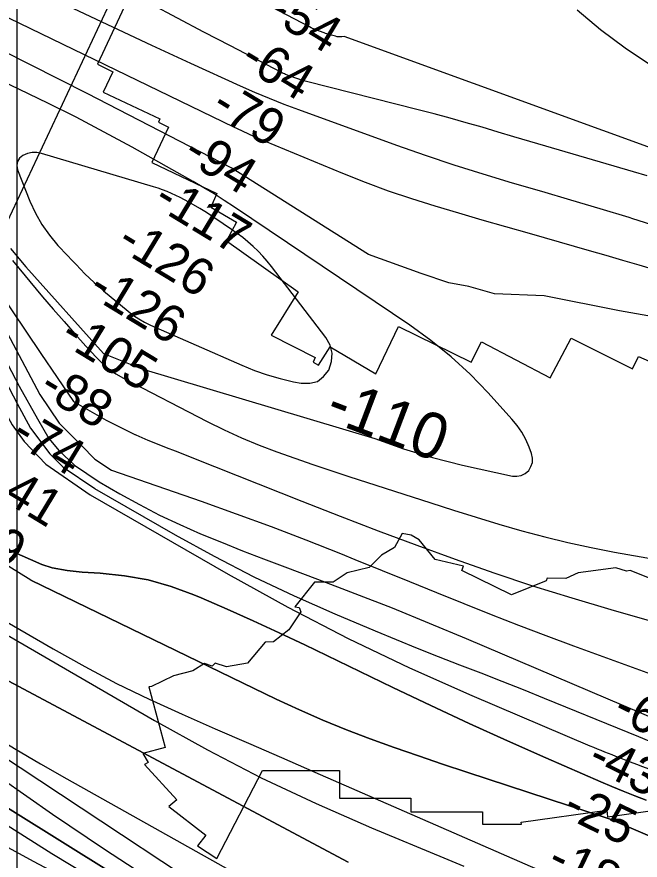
# Model space of a CAD drawing. Extents: x 3263578 to 3301413, y 764927 to 798602.
# Drawn here: x 3280833 to 3281967, y 783206 to 784740 of the extents above; entities that cross this region are included whole.
import ezdxf

# ---------------------------------------------------------------- set-up
doc = ezdxf.new("R2010")
doc.units = 0
for name, color, linetype in [('V-GRID-MAJR', 7, 'Continuous'), ('V-RIVR-RANG', 7, 'Continuous'), ('V-RRAP-RVMT', 7, 'Continuous'), ('V-TOPO-DPTH', 7, 'Continuous'), ('V-TOPO-MAJR', 7, 'Continuous'), ('V-TOPO-MINR', 7, 'Continuous'), ('V-TOPO-MINR-IDEN', 7, 'Continuous'), ('V-TOPO-WATR', 7, 'Continuous')]:
    doc.layers.add(name, color=color, linetype=linetype)

msp = doc.modelspace()

# ---------------------------------------------------------------- linework, layer by layer
at = {"layer": 'V-GRID-MAJR'}
msp.add_spline([(3280833.3, 775830.4), (3280833.3, 781889.1), (3280833.3, 787951.1), (3280833.3, 794013.2), (3280833.3, 794016.5)], degree=3, dxfattribs=at)
at = {"layer": 'V-RIVR-RANG'}
msp.add_line((3280392.6, 783467.5), (3281107, 784989.2), dxfattribs=at)
at = {"layer": 'V-RRAP-RVMT'}
for points in [[(3281046.4, 784797.3), (3280979.3, 784654), (3281007.5, 784640.2), (3280989.8, 784603), (3281092.9, 784554.5), (3281090.5, 784548.9), (3281109, 784539.5), (3281078.4, 784475.5), (3281196.8, 784419.1), (3281185.6, 784394.3), (3281232.2, 784366.9), (3281214.3, 784332.6), (3281344.9, 784239.9), (3281295.8, 784161.2), (3281375.9, 784120.7), (3281371.8, 784111.8), (3281381.8, 784106.6), (3281403, 784140.1), (3281485.8, 784090.8)], [(3281485.8, 784090.8), (3281527, 784176.8)], [(3281527, 784176.8), (3281659.2, 784111.8), (3281678.1, 784148.8), (3281803, 784083.6), (3281841.2, 784155.5), (3281953.1, 784099.7), (3281963.9, 784122.4), (3282083.6, 784070.4), (3282087.1, 784078.4), (3282110.2, 784068.8), (3282133.9, 784114.1), (3282266.9, 784050.1), (3282256.8, 784028.8), (3282374.6, 783971.7), (3282287.6, 783777.8), (3282370.5, 783940), (3282499.2, 783875.4), (3282489.6, 783855.9)], [(3281645.5, 783741.2), (3281593.7, 783753), (3281564.9, 783789), (3281550.3, 783797.4), (3281534, 783800.6), (3281519.7, 783774.8), (3281496.4, 783761), (3281474, 783738.6), (3281433.8, 783728.6), (3281408.6, 783711.6), (3281374.6, 783712.1), (3281338.9, 783667.2)], [(3282111.5, 783656.7), (3282110.1, 783657), (3282097.5, 783653), (3282089.8, 783656.1), (3282083, 783653.5), (3282082.9, 783658.5), (3282075.9, 783663.5), (3282077.8, 783672.5), (3282067.8, 783675), (3282048.2, 783686.4), (3282022.9, 783684.8), (3281991.4, 783708.3), (3281983.8, 783719.1), (3281948.5, 783733.3), (3281941.9, 783731.9), (3281922.7, 783737.9), (3281854.3, 783729), (3281831.8, 783718.8), (3281797.8, 783719.2), (3281796, 783714.6), (3281732.7, 783688.9), (3281642.2, 783733), (3281645.5, 783741.2)], [(3281338.9, 783667.2), (3281346.4, 783665.8), (3281349.5, 783657.8), (3281327.4, 783625.4), (3281299.7, 783603.1), (3281284.5, 783602.8), (3281252.6, 783564.3), (3281214.2, 783558.1), (3281193.8, 783564.7), (3281188, 783558.9), (3281174, 783564), (3281153, 783550.6), (3281117.9, 783541.3), (3281077.9, 783521.9), (3281073.2, 783521.3)], [(3281073.2, 783521.3), (3281102.5, 783411), (3281061.8, 783399.9), (3281072, 783383.8), (3281065, 783379.9), (3281123.8, 783315.9), (3281109.4, 783304), (3281176.9, 783251.7), (3281161.8, 783232), (3281196.8, 783209.1), (3281280, 783369.5)], [(3281280, 783369.5), (3281419.9, 783369.3), (3281419.9, 783318.8), (3281549.9, 783318.7), (3281549.9, 783294.2), (3281679.9, 783294.1), (3281680, 783271.6), (3281751.1, 783271.5), (3281750.4, 783275.4), (3281906.1, 783296.9), (3281907.7, 783285.1), (3282054.3, 783305.5), (3282054.5, 783299.1), (3282060, 783299.2)]]:
    msp.add_lwpolyline(points, dxfattribs=at)
at = {"layer": 'V-TOPO-DPTH'}
for points in [[(3280190.6, 784677.4), (3280301.9, 784587.8), (3280409.7, 784468.3), (3280489.5, 784360), (3280600.9, 784173.4), (3280669.5, 784076.4), (3280702.9, 784014.8), (3280723.3, 783957), (3280738.1, 783910.4), (3280749.2, 783871.3), (3280769.6, 783835.8), (3280782.5, 783813.4), (3280801.1, 783791), (3280821.6, 783768.6), (3280878, 783744)], [(3280878, 783744), (3280821.6, 783768.6), (3280801.1, 783791), (3280782.5, 783813.4), (3280769.6, 783835.8), (3280749.2, 783871.3), (3280738.1, 783910.4), (3280723.3, 783957), (3280702.9, 784014.8), (3280669.5, 784076.4), (3280600.9, 784173.4), (3280489.5, 784360), (3280409.7, 784468.3), (3280301.9, 784587.8), (3280190.6, 784677.4)], [(3280858.2, 783715.4), (3280760.1, 783776.2), (3280709.9, 783828.5), (3280678.4, 783890.1), (3280650.7, 783972.1), (3280615.6, 784089.6), (3280563.6, 784175.4), (3280496.8, 784294.8), (3280443, 784369.4), (3280366.8, 784459.1), (3280296.2, 784541.2), (3280236.8, 784619.6), (3280177.7, 784667.3)], [(3280858.2, 783715.4), (3280760.1, 783776.2), (3280709.9, 783828.5), (3280678.4, 783890.1), (3280650.7, 783972.1), (3280615.6, 784089.6), (3280563.6, 784175.4), (3280496.8, 784294.8), (3280443, 784369.4), (3280366.8, 784459.1), (3280296.2, 784541.2), (3280236.8, 784619.6), (3280177.7, 784667.3)], [(3280878, 783744), (3280897.3, 783738.1), (3280924.4, 783733.1), (3280951.9, 783730), (3280984.6, 783728.2), (3281028.4, 783723.6), (3281071.5, 783715.9), (3281113.5, 783703.8), (3281154.9, 783688.8), (3281168.3, 783683.1), (3281215.7, 783662.6), (3281262.9, 783641.6), (3281309.8, 783619.9), (3281356.5, 783597.8), (3281517.1, 783520.2), (3281586.3, 783487.3), (3281655.7, 783454.9), (3281725.5, 783423.4), (3281795.6, 783392.3), (3281895.2, 783348.9), (3281915.7, 783340.2), (3281936.3, 783331.6), (3281957, 783323.4), (3281977.8, 783315.5)], [(3281977.8, 783315.5), (3281957, 783323.4), (3281936.3, 783331.6), (3281915.7, 783340.2), (3281895.2, 783348.9), (3281795.6, 783392.3), (3281725.5, 783423.4), (3281655.7, 783454.9), (3281586.3, 783487.3), (3281517.1, 783520.2), (3281356.5, 783597.8), (3281309.8, 783619.9), (3281262.9, 783641.6), (3281215.7, 783662.6), (3281168.3, 783683.1), (3281154.9, 783688.8), (3281113.5, 783703.8), (3281071.5, 783715.9), (3281028.4, 783723.6), (3280984.6, 783728.2), (3280951.9, 783730), (3280924.4, 783733.1), (3280897.3, 783738.1), (3280878, 783744)], [(3283979.6, 782089.4), (3282888, 782862.5), (3281912.3, 783281), (3281651.6, 783366.2), (3281607.5, 783380.8), (3281563.5, 783395.7), (3281519.6, 783411.1), (3281475.8, 783426.8), (3281432.4, 783443.3), (3281389.4, 783460.7), (3281346.9, 783479.4), (3281304.8, 783499), (3280858.2, 783715.4)], [(3283979.6, 782089.4), (3282888, 782862.5), (3281912.3, 783281), (3281651.6, 783366.2), (3281607.5, 783380.8), (3281563.5, 783395.7), (3281519.6, 783411.1), (3281475.8, 783426.8), (3281432.4, 783443.3), (3281389.4, 783460.7), (3281346.9, 783479.4), (3281304.8, 783499), (3280858.2, 783715.4)], [(3280807.9, 783643.1), (3280898.7, 783590.4), (3280956.2, 783558.3), (3281014.4, 783527.6), (3281073.5, 783498.9), (3281133.4, 783471.6), (3281193.8, 783445.2), (3281254.1, 783418.9), (3281314.5, 783392.6), (3281374.9, 783366.2), (3281790.2, 783185.2)], [(3280807.9, 783643.1), (3280898.7, 783590.4), (3280956.2, 783558.3), (3281014.4, 783527.6), (3281073.5, 783498.9), (3281133.4, 783471.6), (3281193.8, 783445.2), (3281254.1, 783418.9), (3281314.5, 783392.6), (3281374.9, 783366.2), (3281790.2, 783185.2)], [(3281435.6, 783202.7), (3281389.2, 783227.1), (3280753.8, 783565.5)], [(3281435.6, 783202.7), (3281389.2, 783227.1), (3280753.8, 783565.5)], [(3280689.6, 783473.1), (3281429.6, 782984.4)], [(3280689.6, 783473.1), (3281429.6, 782984.4)], [(3283888.6, 781898.9), (3282782, 782505.4), (3282768.2, 782511.2), (3282754.3, 782516.7), (3282740.3, 782521.9), (3282726.2, 782526.9), (3281705.6, 782792.3), (3281690.7, 782798.6), (3281676, 782805.1), (3281661.5, 782812.2), (3281647.2, 782819.6), (3281449.7, 782925.5), (3281337.4, 782987.1), (3281225.9, 783050.2), (3281115.7, 783115.5), (3281006.4, 783182.2), (3280644.3, 783408)]]:
    msp.add_lwpolyline(points, dxfattribs=at)
at = {"layer": 'V-TOPO-MAJR'}
for points in [[(3281472.5, 784307.7), (3281223, 784465.5), (3280961.7, 784600), (3280857.4, 784653.2), (3280752.9, 784705.9), (3280647.9, 784757.8)], [(3281985.6, 784652.4), (3281939.5, 784683.5), (3281894.9, 784716.5), (3281852.6, 784752.4)], [(3280197.5, 784691.9), (3280326.2, 784597), (3280432.2, 784509.2), (3280486.1, 784458.8), (3280534.4, 784410.2), (3280593.8, 784335.5), (3280666.3, 784249.7), (3280735, 784160.1), (3280766.5, 784104.1), (3280788.7, 784063.1), (3280824, 783997.8), (3280846.3, 783967.9), (3280885.3, 783926.8), (3280966.1, 783870.6)], [(3282227.2, 783780.1), (3282315.8, 783864), (3282359.5, 783954.1), (3282359.6, 784010.9), (3282353, 784054.3), (3282333.1, 784084.4), (3282279.7, 784121.3), (3282186.2, 784158.3), (3282042.7, 784185.4), (3281929.1, 784205.7), (3281792.2, 784232.8), (3281702, 784236.3), (3281655.3, 784249.8), (3281618.6, 784256.6), (3281568.5, 784273.4), (3281472.5, 784307.7)], [(3280824.6, 784297), (3280879.7, 784231.1), (3280899, 784208.4), (3280918.6, 784185.8), (3280938.4, 784163.5), (3280958.5, 784141.3), (3280977.8, 784120.3), (3280988.9, 784109.5), (3281000.6, 784099.5), (3281013.2, 784090.8), (3281026.6, 784083), (3281179.2, 784004), (3281210.2, 783988.7), (3281241.6, 783974.3), (3281273.5, 783961.1), (3281305.8, 783948.8), (3281338.5, 783937.3), (3281371.2, 783926), (3281404, 783915), (3281436.9, 783904.1), (3281585.8, 783855.9), (3281627.1, 783842.8), (3281668.5, 783830), (3281710, 783817.6), (3281751.6, 783805.4), (3281793.4, 783794.2), (3281835.4, 783783.8), (3281877.7, 783774.7), (3281920.2, 783766.6), (3282135, 783728.7)], [(3280966.1, 783870.6), (3281217.4, 783726.3), (3281325.9, 783666.6), (3281435.7, 783609.5), (3281547.4, 783556.3), (3281660.4, 783505.8), (3281875.2, 783414.2), (3281881.8, 783411.5), (3281888.5, 783408.7), (3281895.2, 783406), (3281901.8, 783403.4), (3281908.6, 783400.8), (3281915.3, 783398.2), (3281921.9, 783395.6), (3281928.6, 783392.9), (3281937.6, 783389.4), (3281948.8, 783385), (3281960.1, 783380.7), (3281971.3, 783376.5), (3281982.6, 783372.3), (3282299.1, 783257.3), (3282408.4, 783218.8), (3282518.1, 783181.7)]]:
    msp.add_lwpolyline(points, dxfattribs=at)
at = {"layer": 'V-TOPO-MINR'}
for points in [[(3282369.7, 784362.5), (3281428.1, 784704.7), (3281424.1, 784703.8), (3281420.1, 784703.7), (3281415.9, 784704.2), (3281412.9, 784704.9), (3281410.2, 784705.5), (3281407.5, 784706.2), (3281404.9, 784706.9), (3281402.3, 784707.7), (3281399.6, 784708.5), (3281397, 784709.3), (3281394.5, 784710.2), (3281391.9, 784711.1), (3281377.1, 784716.7), (3281374.1, 784717.9), (3281371, 784719.2), (3281368.1, 784720.6), (3281365.1, 784722.1), (3281121.6, 784850.3)], [(3280279, 784758.1), (3280497.5, 784568.6), (3280620.2, 784456.6), (3280768.8, 784286.7), (3280876.5, 784128), (3280935.9, 784040.3), (3280995.4, 784006.7), (3281047.7, 783980.5)], [(3282009.3, 784355.3), (3281953.4, 784373.1), (3281947, 784375.1), (3281894, 784391), (3281840.9, 784406.9), (3281787.8, 784422.5), (3281734.6, 784438), (3281681.5, 784453.9), (3281628.7, 784470.5), (3281576.2, 784488.1), (3281524, 784506.5), (3281346.1, 784570.9), (3281319.2, 784581), (3281292.5, 784591.5), (3281266, 784602.7), (3281239.7, 784614.3), (3281149.5, 784655.4), (3281078.4, 784688.1), (3281007.4, 784721.3), (3280936.7, 784754.9)], [(3281980, 784451.2), (3281954.6, 784458.1), (3281795.2, 784505.1), (3281766.2, 784513.7), (3281737.3, 784522.3), (3281708.3, 784530.8), (3281679.4, 784539.4), (3281650.4, 784547.8), (3281621.3, 784556), (3281592.1, 784563.8), (3281562.9, 784571.4), (3281359.9, 784622.8), (3281352.8, 784624.7), (3281345.7, 784626.8), (3281338.7, 784629.2), (3281331.8, 784631.7), (3281321.8, 784635.6), (3281319.9, 784636.4), (3281318.1, 784637.2), (3281316.2, 784638.1), (3281314.4, 784639), (3281221.5, 784687.3), (3281173.3, 784712.5), (3281125.1, 784737.8), (3281077, 784763.3)], [(3280256.9, 784738), (3280372.9, 784645.3), (3280529, 784512.7), (3280614.5, 784424.9), (3280737.1, 784283), (3280804, 784186), (3280874.4, 784053.5), (3280909.7, 784001.3), (3280950.6, 783960.2), (3280974.7, 783935.9), (3281005.3, 783915.8)], [(3281995.6, 784279.2), (3281965.4, 784288.3), (3281935.2, 784297.2), (3281905, 784306), (3281874.7, 784314.7), (3281765.5, 784346), (3281722.5, 784358.3), (3281679.6, 784370.7), (3281636.8, 784383.3), (3281593.9, 784395.8), (3281551.3, 784409.2), (3281509, 784423.4), (3281467.2, 784438.9), (3281425.7, 784455.4), (3281285.2, 784513.7), (3281270.7, 784519.8), (3281256.3, 784526.1), (3281242.1, 784532.7), (3281227.9, 784539.4), (3280798.7, 784746.8)], [(3280226.1, 784709.7), (3280361.6, 784613.7), (3280504.8, 784503.4), (3280614.4, 784385.8), (3280701.7, 784285), (3280753.7, 784215.9), (3280794.5, 784148.7), (3280837.2, 784068.5), (3280870.6, 784008.8), (3280891, 783973.4), (3280909.6, 783951), (3280937.4, 783924.8), (3280982.5, 783894.2)], [(3280214.3, 784699), (3280367.1, 784591.3), (3280488, 784492.3), (3280554.9, 784413.9), (3280651.5, 784303.7), (3280735.1, 784201), (3280781.5, 784132), (3280811.1, 784079.8), (3280833.4, 784036.9), (3280857.5, 783992.1), (3280892.8, 783945.4), (3280916.9, 783921.1), (3280974.9, 783882)], [(3280190.6, 784677.4), (3280301.9, 784587.8), (3280409.7, 784468.3), (3280489.5, 784360), (3280600.9, 784173.4), (3280669.5, 784076.4), (3280702.9, 784014.8), (3280723.3, 783957), (3280738.1, 783910.4), (3280749.2, 783871.3), (3280769.6, 783835.8), (3280782.5, 783813.4), (3280801.1, 783791), (3280821.6, 783768.6), (3280878, 783744)], [(3280858.2, 783715.4), (3280760.1, 783776.2), (3280709.9, 783828.5), (3280678.4, 783890.1), (3280650.7, 783972.1), (3280615.6, 784089.6), (3280563.6, 784175.4), (3280496.8, 784294.8), (3280443, 784369.4), (3280366.8, 784459.1), (3280296.2, 784541.2), (3280236.8, 784619.6), (3280177.7, 784667.3)], [(3280821.1, 784318.9), (3280849.3, 784285.3), (3280990.4, 784128.1), (3281060.3, 784099.8), (3281483.9, 783973), (3281536.2, 783954.2), (3281589.4, 783938.6), (3281643.4, 783925), (3281734.4, 783904.9), (3281742.8, 783904.6), (3281750.6, 783905.8), (3281757.6, 783909.6), (3281764.1, 783915), (3281768.3, 783922.2), (3281770.9, 783929.8), (3281771, 783937.7), (3281769.4, 783946), (3281765, 783957.5), (3281758.9, 783971.3), (3281751.8, 783984.5), (3281743.2, 783996.8), (3281733.7, 784008.6), (3281690.5, 784056.2), (3281657.4, 784090), (3281622.9, 784122.1), (3281586.2, 784151.6), (3281548, 784179.4), (3281228.8, 784394.3), (3281210.3, 784406.4), (3281191.7, 784418.2), (3281172.8, 784429.5), (3281153.8, 784440.5), (3281042.5, 784503), (3280991.9, 784530.7), (3280940.9, 784557.6), (3280889.3, 784583.4), (3280837.4, 784608.4), (3280786.8, 784632.1)], [(3281243.8, 784338.8), (3281233.8, 784346.3), (3281223.6, 784353.5), (3281178, 784384.2), (3281175, 784386.2), (3281171.9, 784388.1), (3281168.7, 784390), (3281165.5, 784391.9), (3281145.5, 784403.1), (3281137.8, 784407.3), (3281130, 784411.4), (3281122.2, 784415.2), (3281114.3, 784418.9), (3281106.2, 784422.4), (3281098.1, 784425.6), (3281089.8, 784428.5), (3281081.5, 784431.2), (3280877.8, 784491.8), (3280869, 784493.3), (3280860.4, 784493.4), (3280851.9, 784491.5), (3280843.6, 784488.3), (3280837.7, 784483), (3280833.8, 784477), (3280832.9, 784469.9), (3280834, 784462.1), (3280856.5, 784404.9), (3280866.5, 784383.1), (3280878.1, 784362.3), (3280892, 784343), (3280907.4, 784324.6), (3280924.8, 784306.1), (3280932.7, 784297.8), (3280940.7, 784289.5), (3280948.7, 784281.2), (3280956.8, 784273.1), (3280965, 784265.1), (3280973.3, 784257.2), (3280981.9, 784249.6), (3280990.6, 784242.1), (3281035.6, 784204.6), (3281045.1, 784197.3), (3281054.9, 784190.7), (3281065.2, 784184.9), (3281075.9, 784179.6), (3281242.2, 784106.4), (3281265.2, 784097.2), (3281288.4, 784089), (3281312.1, 784082.2), (3281336.2, 784076.5), (3281350.3, 784073.6), (3281365.7, 784073.7), (3281379.6, 784077.2), (3281390.9, 784085.8), (3281400.7, 784097.8), (3281405.3, 784113.2), (3281406.5, 784128.2), (3281402.6, 784142.8), (3281395.3, 784157), (3281296.2, 784285.9), (3281288.4, 784295.6), (3281280.3, 784305), (3281271.6, 784313.9), (3281262.7, 784322.6), (3281253.3, 784330.8), (3281243.8, 784338.8)], [(3281043.8, 783982.3), (3281055, 783977.2), (3281071.4, 783970.2), (3281087.9, 783963.6), (3281104.5, 783957.1), (3281121.1, 783950.6), (3281137.7, 783944.1), (3281154.2, 783937.5), (3281351.5, 783859.3), (3281420.9, 783832.1), (3281490.5, 783805.4), (3281560.3, 783779.3), (3281630.3, 783753.7), (3281700.6, 783729.1), (3281771.3, 783705.4), (3281842.4, 783683.2), (3281913.8, 783662), (3282053.1, 783622.1)], [(3281005.3, 783915.8), (3281168.1, 783859), (3281231.8, 783836.3), (3281295.3, 783812.9), (3281358.5, 783788.7), (3281421.5, 783763.9), (3281447.9, 783753.3), (3281497.4, 783733.3), (3281547, 783713.2), (3281596.5, 783693.2), (3281646, 783673.1), (3281695.6, 783653.2), (3281745.4, 783633.7), (3281795.3, 783614.8), (3281845.5, 783596.3), (3282012.2, 783535.7)], [(3280982.5, 783894.2), (3281019.9, 783872.7), (3281055.9, 783852.9), (3281092.4, 783834), (3281129.6, 783816.6), (3281167.2, 783800), (3281205.2, 783784.4), (3281243.4, 783769), (3281281.8, 783754.1), (3281320.2, 783739.5), (3281379.6, 783717.4), (3281447.7, 783691.4), (3281515.6, 783664.9), (3281583, 783637.4), (3281650.3, 783609.4), (3282002.2, 783459.7)], [(3280974.3, 783882.4), (3281121, 783798.1), (3281192.1, 783759.1), (3281264, 783721.8), (3281337.3, 783687.1), (3281411.4, 783654.2), (3281484.7, 783623.3), (3281522.9, 783607.5), (3281561.2, 783591.8), (3281599.7, 783576.7), (3281638.3, 783561.7), (3281677, 783546.9), (3281715.5, 783531.8), (3281754, 783516.5), (3281792.3, 783501), (3281944.5, 783438.8), (3281963.7, 783431.1), (3281982.9, 783423.5)], [(3280878, 783744), (3280897.3, 783738.1), (3280924.4, 783733.1), (3280951.9, 783730), (3280984.6, 783728.2), (3281028.4, 783723.6), (3281071.5, 783715.9), (3281113.5, 783703.8), (3281154.9, 783688.8), (3281168.3, 783683.1), (3281215.7, 783662.6), (3281262.9, 783641.6), (3281309.8, 783619.9), (3281356.5, 783597.8), (3281517.1, 783520.2), (3281586.3, 783487.3), (3281655.7, 783454.9), (3281725.5, 783423.4), (3281795.6, 783392.3), (3281895.2, 783348.9), (3281915.7, 783340.2), (3281936.3, 783331.6), (3281957, 783323.4), (3281977.8, 783315.5)], [(3280858.2, 783715.4), (3281304.8, 783499), (3281346.9, 783479.4), (3281389.4, 783460.7), (3281432.4, 783443.3), (3281475.8, 783426.8), (3281519.6, 783411.1), (3281563.5, 783395.7), (3281607.5, 783380.8), (3281651.6, 783366.2), (3281912.3, 783281), (3282888, 782862.5), (3283979.6, 782089.4)], [(3280807.9, 783643.1), (3280898.7, 783590.4), (3280956.2, 783558.3), (3281014.4, 783527.6), (3281073.5, 783498.9), (3281133.4, 783471.6), (3281193.8, 783445.2), (3281254.1, 783418.9), (3281314.5, 783392.6), (3281374.9, 783366.2), (3281790.2, 783185.2)], [(3280796.4, 783626.6), (3281083.4, 783460.1), (3281179.8, 783406.6), (3281277.6, 783355.8), (3281377.3, 783309), (3281478.3, 783264.7), (3281609.5, 783210.5), (3281645.9, 783195.3)], [(3280753.8, 783565.5), (3281389.2, 783227.1), (3281435.6, 783202.7)], [(3280700.9, 783489.4), (3280735.5, 783467.1), (3280782, 783437.9), (3280828.8, 783409.1), (3280876.1, 783381.3), (3280923.8, 783354), (3281707.7, 782914.5), (3281716.8, 782910), (3281726.1, 782906.2), (3281735.7, 782903.4), (3282698.9, 782583.9), (3282734.1, 782571.4), (3282769.1, 782558.2), (3282803.8, 782544.3), (3282838.2, 782529.8), (3283666.8, 782075.8)], [(3280672.4, 783448.4), (3280804, 783355.1), (3280897.8, 783289.9), (3280992.3, 783225.9), (3281088.1, 783163.7), (3281184.6, 783102.6), (3281293.8, 783035), (3281357.2, 782996.5), (3281421.1, 782958.8), (3281485.7, 782922.3), (3281550.7, 782886.6), (3281664.9, 782825.3), (3281673.2, 782821), (3281681.7, 782816.9), (3281690.3, 782813.1), (3281698.9, 782809.4), (3282738.2, 782538.4), (3282759.2, 782530.6), (3282780.1, 782522.2), (3282800.7, 782513.6), (3283832.9, 781945.9)], [(3280644.3, 783408), (3281006.4, 783182.2), (3281115.7, 783115.5), (3281225.9, 783050.2), (3281337.4, 782987.1), (3281449.7, 782925.5), (3281647.2, 782819.6), (3281661.5, 782812.2), (3281676, 782805.1), (3281690.7, 782798.6), (3281705.6, 782792.3), (3282726.2, 782526.9), (3282740.3, 782521.9), (3282754.3, 782516.7), (3282768.2, 782511.2), (3282782, 782505.4), (3283888.6, 781898.9)], [(3280630.5, 783388.1), (3280789.5, 783285.4), (3280896.7, 783218.1), (3281004.9, 783152.6)], [(3280610, 783358.7), (3280657.9, 783326.6), (3280708, 783294.2), (3280758.7, 783262.9), (3280810.4, 783233.1), (3280862.7, 783204.3), (3281611.7, 782807.8), (3281638, 782794.4), (3281664.6, 782781.5), (3281691.6, 782769.6), (3282392.9, 782572.2), (3282414.3, 782567.9), (3282744.5, 782489.1), (3283892.6, 781840)]]:
    msp.add_lwpolyline(points, dxfattribs=at)
at = {"layer": 'V-TOPO-WATR'}
msp.add_lwpolyline([(3280689.6, 783473.1), (3281429.6, 782984.4)], dxfattribs=at)

# ---------------------------------------------------------------- texts
at = {"layer": 'V-RIVR-RANG'}
for s, rotation, p in [('-54', 328.7494, (3281285.9, 784739.1)), ('-64', 328.7494, (3281235.6, 784652.7)), ('-79', 328.7494, (3281183.1, 784567.6)), ('-94', 328.7494, (3281131.5, 784481.9)), ('-117', 328.7494, (3281077.8, 784397.5)), ('-126', 328.7494, (3281011.3, 784320.9)), ('-126', 328.7494, (3280959.3, 784235.5)), ('-105', 328.7494, (3280907.6, 784149.9)), ('-88', 328.7494, (3280869.5, 784056)), ('-74', 328.7494, (3280818.6, 783970)), ('-41', 328.7494, (3280778.7, 783877.2)), ('-39', 328.7494, (3280711.7, 783800.9)), ('-65', 333.8079, (3281913.6, 783466)), ('-43', 333.8079, (3281868, 783377)), ('-25', 333.8079, (3281822.3, 783288)), ('-18', 333.8079, (3281794.1, 783190.4))]:
    msp.add_text(s, height=67, rotation=rotation, dxfattribs=at).set_placement(p)
at = {"layer": 'V-TOPO-MINR-IDEN'}
msp.add_text('-110', height=83, rotation=339.2146, dxfattribs=at).set_placement((3281390.4, 784008.5))

doc.saveas('drawing.dxf')
